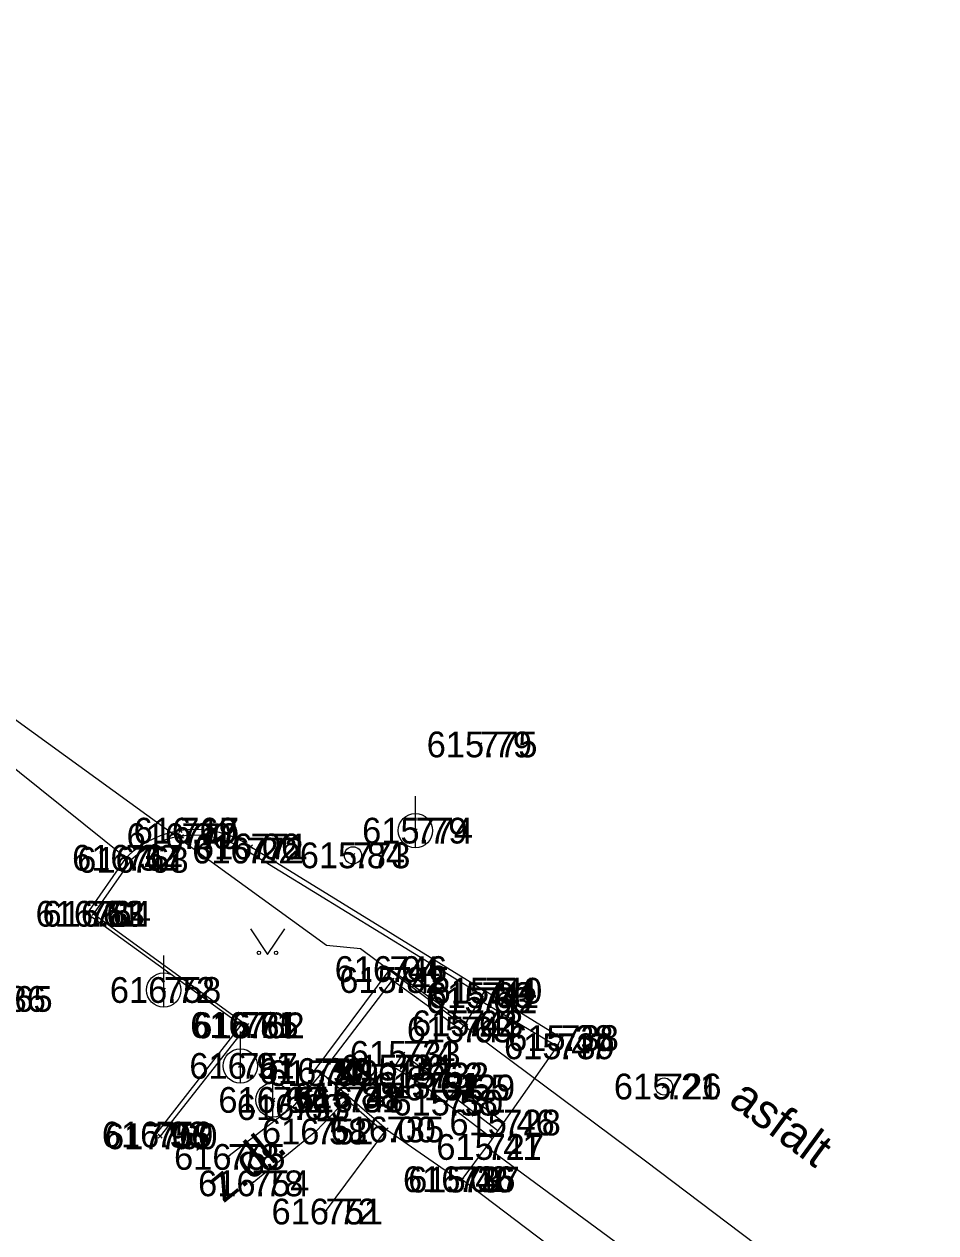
# Model space of a CAD drawing. Extents: x -844765 to -843273, y -997542 to -995529.
# Drawn here: x -843756.09 to -843729.53, y -997146.13 to -997110.94 of the extents above; entities that cross this region are included whole.
import ezdxf

# ---------------------------------------------------------------- set-up
doc = ezdxf.new("R2010")
doc.units = 0
for name, color, linetype in [('Benešův rám', 7, 'Continuous'), ('Betonový strop', 7, 'Continuous'), ('Dno', 7, 'Continuous'), ('Doplněk polohopisu', 7, 'Continuous'), ('Klenba', 7, 'Continuous'), ('Osa', 7, 'Continuous'), ('Popisy budov', 7, 'Continuous'), ('Sítě podzemní nerozlišené', 7, 'Continuous'), ('Výška', 7, 'Continuous'), ('Číslo bodu', 7, 'Continuous'), ('Řezy', 7, 'Continuous')]:
    doc.layers.add(name, color=color, linetype=linetype)

msp = doc.modelspace()

# ---------------------------------------------------------------- linework, layer by layer
at = {"layer": 'Benešův rám'}
for p, q in [((-843743.37, -997140.21), (-843743.22, -997140.03)), ((-843747.43, -997141.48), (-843747.65, -997141.42)), ((-843744.44, -997141.85), (-843745.31, -997141.32)), ((-843746.68, -997142.13), (-843746.7, -997142.25)), ((-843746.7, -997142.25), (-843745.595, -997143.207)), ((-843745.53, -997143.12), (-843746.68, -997142.13))]:
    msp.add_line(p, q, dxfattribs=at)
for points in [[(-843743.22, -997140.03), (-843745.44, -997138.45), (-843747.65, -997141.42)], [(-843747.43, -997141.48), (-843745.36, -997138.77), (-843743.37, -997140.21)], [(-843745.31, -997141.32), (-843745.05, -997140.92), (-843744.22, -997141.55), (-843744.44, -997141.85)]]:
    msp.add_lwpolyline(points, dxfattribs=at)
at = {"layer": 'Betonový strop'}
for p, q in [((-843759.25, -997130.3), (-843753.12, -997135.21)), ((-843743.22, -997140.03), (-843742.81, -997139.36)), ((-843740.56, -997140.7), (-843740.44, -997140.46)), ((-843740.56, -997140.7), (-843742.13, -997142.92)), ((-843746.68, -997142.13), (-843747.43, -997141.48)), ((-843743.81, -997142.34), (-843744.44, -997141.85)), ((-843743.81, -997142.34), (-843743.46, -997141.9)), ((-843742.13, -997142.92), (-843743.46, -997141.9)), ((-843743.635, -997142.12), (-843742.29, -997143.152)), ((-843743.81, -997142.34), (-843742.45, -997143.383)), ((-843742.13, -997142.92), (-843742.62, -997143.63)), ((-843743.33, -997144.58), (-843742.62, -997143.63))]:
    msp.add_line(p, q, dxfattribs=at)
for points in [[(-843749.49, -997134.88), (-843742.67, -997139.08)], [(-843752.25, -997143.27), (-843749.77, -997140.08), (-843754.25, -997136.84), (-843753.12, -997135.21)], [(-843742.76, -997139.21), (-843749.62, -997135)], [(-843752.97, -997135.27), (-843754.07, -997136.84), (-843749.59, -997140.09), (-843752.13, -997143.32)], [(-843740.44, -997140.46), (-843742.67, -997139.08), (-843742.76, -997139.21), (-843742.81, -997139.36), (-843740.56, -997140.7)], [(-843747.43, -997141.48), (-843748.27, -997142.47), (-843750.15, -997143.92)], [(-843746.7, -997142.25), (-843747.59, -997143.18), (-843749.45, -997144.69)], [(-843742.62, -997143.63), (-843733.23, -997150.54), (-843734.02, -997151.61)]]:
    msp.add_lwpolyline(points, dxfattribs=at)
for centre, radius, start, end in [((-843751.103, -997137.269), 2.883, 55.9823, 134.4066), ((-843751.121, -997137.299), 2.746, 56.8698, 132.346)]:
    msp.add_arc(centre, radius, start, end, dxfattribs=at)
at = {"layer": 'Dno'}
msp.add_lwpolyline([(-843749.499, -997137.277), (-843748.999, -997138.027), (-843748.499, -997137.277)], dxfattribs=at)
for centre in [(-843749.249, -997137.977), (-843748.749, -997137.977)]:
    msp.add_circle(centre, 0.05, dxfattribs=at)
at = {"layer": 'Doplněk polohopisu'}
for p, q in [((-843744.69, -997134.92), (-843744.69, -997133.42)), ((-843752.02, -997139.56), (-843752.02, -997138.06)), ((-843749.79, -997141.77), (-843749.79, -997140.27)), ((-843748.84, -997142.76), (-843748.84, -997141.26))]:
    msp.add_line(p, q, dxfattribs=at)
for centre in [(-843744.69, -997134.42), (-843752.02, -997139.06), (-843749.79, -997141.27), (-843748.84, -997142.26)]:
    msp.add_circle(centre, 0.5, dxfattribs=at)
at = {"layer": 'Klenba'}
for p, q in [((-843747.31, -997145.51), (-843745.53, -997143.12)), ((-843745.53, -997143.12), (-843743.45, -997144.57)), ((-843743.45, -997144.57), (-843743.33, -997144.58)), ((-843743.33, -997144.58), (-843734.02, -997151.61))]:
    msp.add_line(p, q, dxfattribs=at)
at = {"layer": 'Osa'}
msp.add_lwpolyline([(-843652.733, -997208.733), (-843685.02, -997184.17), (-843714.345, -997161.915), (-843737.99, -997144.048), (-843746.288, -997137.863), (-843747.28, -997137.765), (-843770.695, -997120.79), (-843797.765, -997100.1), (-843802.485, -997096.6), (-843818.53, -997084.865), (-843834.64, -997072.98), (-843843.67, -997065.86), (-843850.655, -997061.13), (-843858.565, -997054.8), (-843873.555, -997041.845), (-843881.268, -997036.038), (-843889.863, -997029.565), (-843897.978, -997023.38), (-843905.21, -997017.86), (-843921.14, -997005.98)], dxfattribs=at)
at = {"layer": 'Popisy budov'}
for centre in [(-843746.51, -997135.14), (-843737.45, -997141.87)]:
    msp.add_circle(centre, 0.25, dxfattribs=at)
at = {"layer": 'Sítě podzemní nerozlišené'}
for p, q in [((-843742.81, -997131.91), (-843742.86, -997131.86)), ((-843742.81, -997131.91), (-843742.86, -997131.96)), ((-843742.81, -997131.91), (-843742.76, -997131.86)), ((-843742.81, -997131.91), (-843742.76, -997131.96)), ((-843751.54, -997134.42), (-843751.59, -997134.37)), ((-843751.54, -997134.42), (-843751.59, -997134.47)), ((-843751.5, -997134.58), (-843751.55, -997134.53)), ((-843751.54, -997134.42), (-843751.49, -997134.37)), ((-843751.54, -997134.42), (-843751.49, -997134.47)), ((-843751.5, -997134.58), (-843751.45, -997134.53)), ((-843744.69, -997134.42), (-843744.74, -997134.37)), ((-843744.69, -997134.42), (-843744.74, -997134.47)), ((-843744.69, -997134.42), (-843744.64, -997134.37)), ((-843744.69, -997134.42), (-843744.64, -997134.47)), ((-843751.5, -997134.58), (-843751.55, -997134.63)), ((-843751.5, -997134.58), (-843751.45, -997134.63)), ((-843749.49, -997134.88), (-843749.54, -997134.83)), ((-843749.49, -997134.88), (-843749.54, -997134.93)), ((-843749.49, -997134.88), (-843749.44, -997134.83)), ((-843749.49, -997134.88), (-843749.44, -997134.93)), ((-843753.12, -997135.21), (-843753.17, -997135.16)), ((-843753.12, -997135.21), (-843753.17, -997135.26)), ((-843753.12, -997135.21), (-843753.07, -997135.16)), ((-843753.12, -997135.21), (-843753.07, -997135.26)), ((-843752.97, -997135.27), (-843753.02, -997135.22)), ((-843752.97, -997135.27), (-843752.92, -997135.22)), ((-843749.62, -997135), (-843749.67, -997134.95)), ((-843749.62, -997135), (-843749.67, -997135.05)), ((-843749.62, -997135), (-843749.57, -997134.95)), ((-843749.62, -997135), (-843749.57, -997135.05)), ((-843746.51, -997135.14), (-843746.56, -997135.09)), ((-843746.51, -997135.14), (-843746.56, -997135.19)), ((-843746.51, -997135.14), (-843746.46, -997135.09)), ((-843746.51, -997135.14), (-843746.46, -997135.19)), ((-843752.97, -997135.27), (-843753.02, -997135.32)), ((-843752.97, -997135.27), (-843752.92, -997135.32)), ((-843754.25, -997136.84), (-843754.3, -997136.79)), ((-843754.25, -997136.84), (-843754.3, -997136.89)), ((-843754.25, -997136.84), (-843754.2, -997136.79)), ((-843754.25, -997136.84), (-843754.2, -997136.89)), ((-843754.07, -997136.84), (-843754.12, -997136.79)), ((-843754.07, -997136.84), (-843754.12, -997136.89)), ((-843754.07, -997136.84), (-843754.02, -997136.79)), ((-843754.07, -997136.84), (-843754.02, -997136.89)), ((-843745.44, -997138.45), (-843745.49, -997138.4)), ((-843745.44, -997138.45), (-843745.39, -997138.4)), ((-843745.44, -997138.45), (-843745.49, -997138.5)), ((-843745.44, -997138.45), (-843745.39, -997138.5)), ((-843745.36, -997138.77), (-843745.41, -997138.72)), ((-843745.36, -997138.77), (-843745.31, -997138.72)), ((-843752.02, -997139.06), (-843752.07, -997139.01)), ((-843752.02, -997139.06), (-843752.07, -997139.11)), ((-843752.02, -997139.06), (-843751.97, -997139.01)), ((-843752.02, -997139.06), (-843751.97, -997139.11)), ((-843745.36, -997138.77), (-843745.41, -997138.82)), ((-843745.36, -997138.77), (-843745.31, -997138.82)), ((-843742.67, -997139.08), (-843742.72, -997139.03)), ((-843742.67, -997139.08), (-843742.72, -997139.13)), ((-843742.67, -997139.08), (-843742.62, -997139.03)), ((-843742.67, -997139.08), (-843742.62, -997139.13)), ((-843742.81, -997139.36), (-843742.86, -997139.31)), ((-843742.81, -997139.36), (-843742.86, -997139.41)), ((-843742.76, -997139.21), (-843742.81, -997139.16)), ((-843742.76, -997139.21), (-843742.81, -997139.26)), ((-843742.81, -997139.36), (-843742.76, -997139.31)), ((-843742.81, -997139.36), (-843742.76, -997139.41)), ((-843742.76, -997139.21), (-843742.71, -997139.16)), ((-843742.76, -997139.21), (-843742.71, -997139.26)), ((-843749.77, -997140.08), (-843749.82, -997140.03)), ((-843749.77, -997140.08), (-843749.82, -997140.13)), ((-843749.77, -997140.08), (-843749.72, -997140.03)), ((-843749.77, -997140.08), (-843749.72, -997140.13)), ((-843749.59, -997140.09), (-843749.64, -997140.04)), ((-843749.59, -997140.09), (-843749.64, -997140.14)), ((-843749.59, -997140.09), (-843749.54, -997140.04)), ((-843749.59, -997140.09), (-843749.54, -997140.14)), ((-843743.37, -997140.21), (-843743.42, -997140.16)), ((-843743.37, -997140.21), (-843743.32, -997140.16)), ((-843743.22, -997140.03), (-843743.27, -997139.98)), ((-843743.22, -997140.03), (-843743.27, -997140.08)), ((-843743.22, -997140.03), (-843743.17, -997139.98)), ((-843743.22, -997140.03), (-843743.17, -997140.08)), ((-843743.37, -997140.21), (-843743.42, -997140.26)), ((-843743.37, -997140.21), (-843743.32, -997140.26)), ((-843740.44, -997140.46), (-843740.49, -997140.41)), ((-843740.44, -997140.46), (-843740.49, -997140.51)), ((-843740.44, -997140.46), (-843740.39, -997140.41)), ((-843740.44, -997140.46), (-843740.39, -997140.51)), ((-843745.05, -997140.92), (-843745.1, -997140.87)), ((-843745.05, -997140.92), (-843745, -997140.87)), ((-843740.56, -997140.7), (-843740.61, -997140.65)), ((-843740.56, -997140.7), (-843740.61, -997140.75)), ((-843740.56, -997140.7), (-843740.51, -997140.65)), ((-843740.56, -997140.7), (-843740.51, -997140.75)), ((-843749.79, -997141.27), (-843749.84, -997141.22)), ((-843749.79, -997141.27), (-843749.74, -997141.22)), ((-843745.05, -997140.92), (-843745.1, -997140.97)), ((-843745.05, -997140.92), (-843745, -997140.97)), ((-843749.79, -997141.27), (-843749.84, -997141.32)), ((-843749.79, -997141.27), (-843749.74, -997141.32)), ((-843747.65, -997141.42), (-843747.7, -997141.37)), ((-843747.65, -997141.42), (-843747.7, -997141.47)), ((-843747.65, -997141.42), (-843747.6, -997141.37)), ((-843747.65, -997141.42), (-843747.6, -997141.47)), ((-843747.43, -997141.48), (-843747.48, -997141.43)), ((-843747.43, -997141.48), (-843747.48, -997141.53)), ((-843747.43, -997141.48), (-843747.38, -997141.43)), ((-843747.43, -997141.48), (-843747.38, -997141.53)), ((-843745.31, -997141.32), (-843745.36, -997141.27)), ((-843745.31, -997141.32), (-843745.36, -997141.37)), ((-843745.31, -997141.32), (-843745.26, -997141.27)), ((-843745.31, -997141.32), (-843745.26, -997141.37)), ((-843744.22, -997141.55), (-843744.27, -997141.5)), ((-843744.22, -997141.55), (-843744.27, -997141.6)), ((-843744.22, -997141.55), (-843744.17, -997141.5)), ((-843744.22, -997141.55), (-843744.17, -997141.6)), ((-843744.44, -997141.85), (-843744.49, -997141.8)), ((-843744.44, -997141.85), (-843744.49, -997141.9)), ((-843744.44, -997141.85), (-843744.39, -997141.8)), ((-843744.44, -997141.85), (-843744.39, -997141.9)), ((-843743.46, -997141.9), (-843743.51, -997141.85)), ((-843743.46, -997141.9), (-843743.51, -997141.95)), ((-843743.46, -997141.9), (-843743.41, -997141.85)), ((-843743.46, -997141.9), (-843743.41, -997141.95)), ((-843737.45, -997141.87), (-843737.5, -997141.82)), ((-843737.45, -997141.87), (-843737.5, -997141.92)), ((-843737.45, -997141.87), (-843737.4, -997141.82)), ((-843737.45, -997141.87), (-843737.4, -997141.92)), ((-843748.84, -997142.26), (-843748.89, -997142.21)), ((-843748.84, -997142.26), (-843748.89, -997142.31)), ((-843748.84, -997142.26), (-843748.79, -997142.21)), ((-843748.84, -997142.26), (-843748.79, -997142.31)), ((-843746.7, -997142.25), (-843746.75, -997142.2)), ((-843746.7, -997142.25), (-843746.75, -997142.3)), ((-843746.68, -997142.13), (-843746.73, -997142.08)), ((-843746.68, -997142.13), (-843746.73, -997142.18)), ((-843746.7, -997142.25), (-843746.65, -997142.2)), ((-843746.7, -997142.25), (-843746.65, -997142.3)), ((-843746.68, -997142.13), (-843746.63, -997142.08)), ((-843746.68, -997142.13), (-843746.63, -997142.18)), ((-843748.27, -997142.47), (-843748.32, -997142.42)), ((-843748.27, -997142.47), (-843748.32, -997142.52)), ((-843748.27, -997142.47), (-843748.22, -997142.42)), ((-843748.27, -997142.47), (-843748.22, -997142.52)), ((-843743.81, -997142.34), (-843743.86, -997142.29)), ((-843743.81, -997142.34), (-843743.86, -997142.39)), ((-843743.81, -997142.34), (-843743.76, -997142.29)), ((-843743.81, -997142.34), (-843743.76, -997142.39)), ((-843742.13, -997142.92), (-843742.18, -997142.87)), ((-843742.13, -997142.92), (-843742.18, -997142.97)), ((-843742.13, -997142.92), (-843742.08, -997142.87)), ((-843742.13, -997142.92), (-843742.08, -997142.97)), ((-843752.25, -997143.27), (-843752.3, -997143.22)), ((-843752.25, -997143.27), (-843752.3, -997143.32)), ((-843752.25, -997143.27), (-843752.2, -997143.22)), ((-843752.25, -997143.27), (-843752.2, -997143.32)), ((-843752.13, -997143.32), (-843752.18, -997143.27)), ((-843752.13, -997143.32), (-843752.18, -997143.37)), ((-843752.13, -997143.32), (-843752.08, -997143.27)), ((-843752.13, -997143.32), (-843752.08, -997143.37)), ((-843747.59, -997143.18), (-843747.64, -997143.13)), ((-843747.59, -997143.18), (-843747.64, -997143.23)), ((-843747.59, -997143.18), (-843747.54, -997143.13)), ((-843747.59, -997143.18), (-843747.54, -997143.23)), ((-843745.53, -997143.12), (-843745.58, -997143.07)), ((-843745.53, -997143.12), (-843745.58, -997143.17)), ((-843745.53, -997143.12), (-843745.48, -997143.07)), ((-843745.53, -997143.12), (-843745.48, -997143.17)), ((-843742.62, -997143.63), (-843742.67, -997143.58)), ((-843742.62, -997143.63), (-843742.67, -997143.68)), ((-843742.62, -997143.63), (-843742.57, -997143.58)), ((-843742.62, -997143.63), (-843742.57, -997143.68)), ((-843750.15, -997143.92), (-843750.2, -997143.87)), ((-843750.15, -997143.92), (-843750.2, -997143.97)), ((-843750.15, -997143.92), (-843750.1, -997143.87)), ((-843750.15, -997143.92), (-843750.1, -997143.97)), ((-843749.45, -997144.69), (-843749.5, -997144.64)), ((-843749.45, -997144.69), (-843749.5, -997144.74)), ((-843749.45, -997144.69), (-843749.4, -997144.64)), ((-843749.45, -997144.69), (-843749.4, -997144.74)), ((-843743.45, -997144.57), (-843743.5, -997144.52)), ((-843743.45, -997144.57), (-843743.5, -997144.62)), ((-843743.45, -997144.57), (-843743.4, -997144.52)), ((-843743.45, -997144.57), (-843743.4, -997144.62)), ((-843743.33, -997144.58), (-843743.38, -997144.53)), ((-843743.33, -997144.58), (-843743.38, -997144.63)), ((-843743.33, -997144.58), (-843743.28, -997144.53)), ((-843743.33, -997144.58), (-843743.28, -997144.63)), ((-843747.31, -997145.51), (-843747.36, -997145.46)), ((-843747.31, -997145.51), (-843747.36, -997145.56)), ((-843747.31, -997145.51), (-843747.26, -997145.46)), ((-843747.31, -997145.51), (-843747.26, -997145.56))]:
    msp.add_line(p, q, dxfattribs=at)

# ---------------------------------------------------------------- texts
at = {"layer": 'Výška'}
for s, rotation, p in [('asfalt', 323.651, (-843735.608, -997142.366)), ('z.dl.', 39.0707, (-843750.283, -997145.285))]:
    msp.add_text(s, height=1, rotation=rotation, dxfattribs=at).set_placement(p)
at = {"layer": 'Číslo bodu'}
for s, p in [('775', (-843742.81, -997132.285)), ('769', (-843751.54, -997134.795)), ('774', (-843744.69, -997134.795)), ('770', (-843751.5, -997134.955)), ('771', (-843749.49, -997135.255)), ('767', (-843753.12, -997135.585)), ('768', (-843752.97, -997135.645)), ('772', (-843749.62, -997135.375)), ('773', (-843746.51, -997135.515)), ('763', (-843754.25, -997137.215)), ('764', (-843754.07, -997137.215)), ('746', (-843745.44, -997138.825)), ('745', (-843745.36, -997139.145)), ('758', (-843752.02, -997139.435)), ('740', (-843742.67, -997139.455)), ('765', (-843756.93, -997139.695)), ('742', (-843742.81, -997139.735)), ('741', (-843742.76, -997139.585)), ('761', (-843749.77, -997140.455)), ('762', (-843749.59, -997140.465)), ('743', (-843743.22, -997140.405)), ('744', (-843743.37, -997140.585)), ('738', (-843740.44, -997140.835)), ('739', (-843740.56, -997141.075)), ('733', (-843745.05, -997141.295)), ('757', (-843749.79, -997141.645)), ('750', (-843747.65, -997141.795)), ('749', (-843747.43, -997141.855)), ('734', (-843745.31, -997141.695)), ('732', (-843744.22, -997141.925)), ('731', (-843744.44, -997142.225)), ('729', (-843743.46, -997142.275)), ('726', (-843737.45, -997142.245)), ('756', (-843748.84, -997142.635)), ('748', (-843746.7, -997142.625)), ('747', (-843746.68, -997142.505)), ('753', (-843748.27, -997142.845)), ('730', (-843743.81, -997142.715)), ('728', (-843742.13, -997143.295)), ('759', (-843752.25, -997143.645)), ('760', (-843752.13, -997143.695)), ('752', (-843747.59, -997143.555)), ('735', (-843745.53, -997143.495)), ('727', (-843742.62, -997144.005)), ('755', (-843750.15, -997144.295)), ('754', (-843749.45, -997145.065)), ('736', (-843743.45, -997144.945)), ('737', (-843743.33, -997144.955)), ('751', (-843747.31, -997145.885))]:
    msp.add_text(s, height=0.75, dxfattribs=at).set_placement(p)
at = {"layer": 'Řezy'}
for s, p in [('615.79', (-843744.363, -997132.285)), ('616.17', (-843752.898, -997134.795)), ('615.79', (-843746.243, -997134.795)), ('616.30', (-843753.103, -997134.955)), ('616.06', (-843751.114, -997135.255)), ('616.32', (-843754.691, -997135.585)), ('616.44', (-843754.541, -997135.645)), ('616.22', (-843751.191, -997135.375)), ('615.84', (-843748.06, -997135.515)), ('616.61', (-843755.753, -997137.215)), ('616.81', (-843755.552, -997137.215)), ('616.04', (-843747.043, -997138.825)), ('615.82', (-843746.91, -997139.145)), ('616.72', (-843753.591, -997139.435)), ('615.54', (-843744.22, -997139.455)), ('616.86', (-843758.521, -997139.695)), ('615.63', (-843744.381, -997139.735)), ('615.63', (-843744.331, -997139.585)), ('616.71', (-843751.252, -997140.455)), ('616.85', (-843751.161, -997140.465)), ('615.62', (-843744.791, -997140.405)), ('615.63', (-843744.941, -997140.585)), ('615.38', (-843741.99, -997140.835)), ('615.47', (-843742.11, -997141.075)), ('615.74', (-843746.6, -997141.295)), ('616.91', (-843751.275, -997141.645)), ('616.30', (-843749.253, -997141.795)), ('615.88', (-843748.98, -997141.855)), ('615.86', (-843746.881, -997141.695)), ('615.62', (-843745.791, -997141.925)), ('615.61', (-843745.922, -997142.225)), ('615.55', (-843745.01, -997142.275)), ('615.21', (-843738.912, -997142.245)), ('616.62', (-843750.431, -997142.635)), ('615.88', (-843748.23, -997142.505)), ('616.31', (-843748.182, -997142.625)), ('616.60', (-843749.894, -997142.845)), ('615.58', (-843745.36, -997142.715)), ('615.46', (-843743.701, -997143.295)), ('616.93', (-843753.824, -997143.645)), ('617.06', (-843753.733, -997143.695)), ('616.58', (-843749.161, -997143.555)), ('616.00', (-843747.166, -997143.495)), ('615.41', (-843744.082, -997144.005)), ('616.78', (-843751.721, -997144.295)), ('616.78', (-843751.021, -997145.065)), ('616.02', (-843745.053, -997144.945)), ('615.46', (-843744.901, -997144.955)), ('616.72', (-843748.881, -997145.885))]:
    msp.add_text(s, height=0.75, dxfattribs=at).set_placement(p)

doc.saveas('drawing.dxf')
